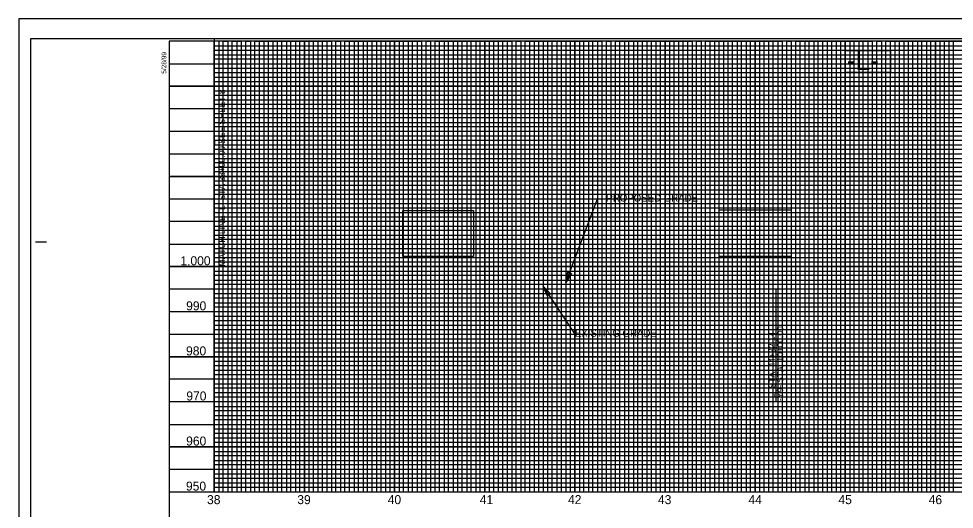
# Model space of a CAD drawing. Extents: x 1626113 to 1628102, y 900759 to 901859.
# Drawn here: x 1626113 to 1627151, y 901315 to 901859 of the extents above; entities that cross this region are included whole.
import ezdxf

# ---------------------------------------------------------------- set-up
doc = ezdxf.new("R2010")
doc.units = 0
for name, color, linetype in [('Default', 7, 'Continuous'), ('Matchline', 7, 'Continuous'), ('Matchline Text', 7, 'Continuous'), ('Prop DSN Text', 7, 'Continuous'), ('Prop PHM Black Shape', 7, 'Continuous'), ('Prop Plan Preparation Cover Label', 7, 'Continuous'), ('Scratch_Level_1', 7, 'Continuous'), ('Sheet Cutting Line CELL', 7, 'Continuous'), ('Sheet DOT Grid CELL', 7, 'Continuous'), ('Sheet Layout Profile Border Port 1', 7, 'Continuous'), ('Sheet Plot Border Inside CELL', 7, 'Continuous'), ('Sheet Plot Border Outside CELL', 7, 'Continuous'), ('Sheet Profile CELL', 7, 'Continuous'), ('Sheet Profile Grid Major CELL', 7, 'Continuous'), ('Sheet Profile Grid Middle CELL', 7, 'Continuous'), ('Typical Terminator CELL', 7, 'Continuous')]:
    doc.layers.add(name, color=color, linetype=linetype)

msp = doc.modelspace()

# ---------------------------------------------------------------- linework, layer by layer
at = {"layer": 'Matchline'}
msp.add_line((1626329.9, 901837), (1626329.9, 901334.4), dxfattribs=at)
at = {"layer": 'Prop DSN Text'}
for p, q in [((1626719.9, 901566.7), (1626754.9, 901659.4)), ((1626754.9, 901659.4), (1626764.9, 901659.4)), ((1626694.9, 901562.3), (1626729.9, 901509.4)), ((1626729.9, 901509.4), (1626734.9, 901509.4))]:
    msp.add_line(p, q, dxfattribs=at)
msp.add_lwpolyline([(1627029.9, 901824.3), (1627079.9, 901824.3), (1627079.9, 901799.4), (1627029.9, 901799.4)], close=True, dxfattribs=at)
msp.add_lwpolyline([(1626952.9, 901559.1), (1626952.9, 901434.8)], dxfattribs=at)
at = {"layer": 'Prop PHM Black Shape'}
for points in [[(1627029.9, 901824), (1627079.9, 901824), (1627079.9, 901799.2), (1627029.9, 901799.2)], [(1626539.2, 901646.5), (1626617.4, 901646.5), (1626617.4, 901595.5), (1626539.2, 901595.5)], [(1626889.9, 901647.1), (1626969.9, 901647.1), (1626969.9, 901595.6), (1626889.9, 901595.6)]]:
    msp.add_lwpolyline(points, close=True, dxfattribs=at)
at = {"layer": 'Prop Plan Preparation Cover Label'}
for p, q in [((1626329.9, 901829.2), (1627579.9, 901829.2)), ((1626329.9, 901824.2), (1626329.9, 901824.2)), ((1627579.9, 901824.2), (1626329.9, 901823.8)), ((1626329.9, 901819.2), (1627579.9, 901819.2)), ((1627579.9, 901699.2), (1626329.9, 901699.2)), ((1627579.9, 901694.2), (1626329.9, 901694.2)), ((1627579.9, 901689.2), (1626329.9, 901689.2)), ((1626329.9, 901679.2), (1627579.9, 901679.2)), ((1627579.9, 901674.2), (1626329.9, 901674.2)), ((1626329.9, 901669.2), (1627729.9, 901669.2)), ((1627729.9, 901649.2), (1626329.9, 901649.2)), ((1626329.9, 901644.2), (1627729.9, 901644.2)), ((1627729.9, 901624.2), (1626329.9, 901624.2)), ((1626329.9, 901619.2), (1627729.9, 901619.2)), ((1627729.9, 901599.2), (1626329.9, 901599.2)), ((1626329.9, 901594.2), (1627729.9, 901594.2)), ((1627729.9, 901589.2), (1626329.9, 901589.2)), ((1626329.9, 901579.2), (1627729.9, 901579.2)), ((1627729.9, 901574.2), (1626329.9, 901574.2)), ((1626329.9, 901569.2), (1627729.9, 901569.2)), ((1627729.9, 901564.2), (1626329.9, 901564.2)), ((1626329.9, 901554.2), (1627729.9, 901554.2)), ((1627729.9, 901549.2), (1626329.9, 901549.2)), ((1626329.9, 901544.2), (1627729.9, 901544.2)), ((1627729.9, 901539.2), (1626329.9, 901539.2)), ((1626329.9, 901529.2), (1627729.9, 901529.2)), ((1627729.9, 901524.2), (1626329.9, 901524.2)), ((1626329.9, 901519.2), (1627729.9, 901519.2)), ((1627729.9, 901514.2), (1626329.9, 901514.2)), ((1626329.9, 901504.2), (1627729.9, 901504.2)), ((1627729.9, 901499.2), (1626329.9, 901499.2)), ((1626329.9, 901494.2), (1627729.9, 901494.2)), ((1627729.9, 901489.2), (1626329.9, 901489.2)), ((1626329.9, 901479.2), (1627729.9, 901479.2)), ((1627729.9, 901474.2), (1626329.9, 901474.2)), ((1626329.9, 901469.2), (1627729.9, 901469.2)), ((1627729.9, 901464.2), (1626329.9, 901464.2)), ((1626329.9, 901454.2), (1627729.9, 901454.2)), ((1627729.9, 901449.2), (1626329.9, 901449.2)), ((1627729.9, 901444.2), (1626329.9, 901444.2)), ((1627729.9, 901439.2), (1626329.9, 901439.2)), ((1626329.9, 901429.2), (1627729.9, 901429.2)), ((1627729.9, 901424.2), (1626329.9, 901424.2)), ((1626329.9, 901419.2), (1627729.9, 901419.2)), ((1627729.9, 901414.2), (1626329.9, 901414.2)), ((1626329.9, 901404.2), (1627729.9, 901404.2)), ((1627729.9, 901399.2), (1626329.9, 901399.2)), ((1626329.9, 901394.2), (1627729.9, 901394.2)), ((1627729.9, 901389.2), (1626329.9, 901389.2)), ((1626329.9, 901379.2), (1627729.9, 901379.2)), ((1627729.9, 901374.2), (1626329.9, 901374.2)), ((1626329.9, 901369.2), (1627729.9, 901369.2)), ((1627729.9, 901364.2), (1626329.9, 901364.2)), ((1626329.9, 901354.2), (1627729.9, 901354.2)), ((1627729.9, 901349.2), (1626329.9, 901349.2)), ((1626329.9, 901344.2), (1627729.9, 901344.2))]:
    msp.add_line(p, q, dxfattribs=at)
for points in [[(1626334.9, 901834.2), (1626334.9, 901334.2), (1626339.9, 901334.2), (1626339.9, 901834.2), (1626344.9, 901834.2), (1626344.9, 901334.2), (1626349.9, 901334.2), (1626349.9, 901834.2), (1626359.9, 901834.2), (1626359.9, 901334.2), (1626364.9, 901334.2), (1626364.9, 901834.2), (1626369.9, 901834.2), (1626369.9, 901334.2), (1626374.9, 901334.2), (1626384.9, 901334.2), (1626389.9, 901334.2), (1626389.9, 901834.2), (1626394.9, 901834.2), (1626394.9, 901334.2), (1626399.9, 901334.2), (1626399.9, 901834.2), (1626409.9, 901834.2), (1626409.9, 901334.2), (1626414.9, 901334.2), (1626414.9, 901834.2), (1626419.9, 901834.2), (1626419.9, 901334.2), (1626424.9, 901334.2), (1626424.9, 901834.2), (1626434.9, 901834.2), (1626434.9, 901334.2), (1626439.9, 901334.2), (1626439.9, 901834.2), (1626444.9, 901834.2), (1626444.9, 901334.2), (1626449.9, 901334.2), (1626449.9, 901834.2), (1626459.9, 901834.2), (1626459.9, 901334.2), (1626464.9, 901334.2), (1626464.9, 901834.2), (1626469.9, 901834.2), (1626469.9, 901334.2), (1626474.9, 901334.2), (1626474.9, 901834.2), (1626484.9, 901834.2), (1626484.9, 901334.2), (1626489.9, 901334.2), (1626489.9, 901834.2), (1626494.9, 901834.2), (1626494.9, 901334.2), (1626499.9, 901334.2), (1626499.9, 901834.2), (1626509.9, 901834.2), (1626509.9, 901334.2), (1626514.9, 901334.2), (1626514.9, 901834.2), (1626519.9, 901834.2), (1626519.9, 901334.2), (1626524.9, 901334.2), (1626524.9, 901834.2), (1626534.9, 901834.2), (1626534.9, 901334.2), (1626539.9, 901334.2), (1626539.9, 901834.2), (1626544.9, 901834.2), (1626544.9, 901334.2)], [(1626374.9, 901334.2), (1626374.9, 901834.2), (1626384.9, 901834.2), (1626384.9, 901334.2)], [(1626544.9, 901334.2), (1626549.9, 901334.2), (1626549.9, 901834.2), (1626559.9, 901834.2), (1626559.9, 901334.2), (1626564.9, 901334.2), (1626564.9, 901834.2), (1626569.9, 901834.2), (1626569.9, 901334.2), (1626574.9, 901334.2), (1626574.9, 901834.2), (1626584.9, 901834.2), (1626584.9, 901334.2), (1626589.9, 901334.2), (1626589.9, 901834.2), (1626594.9, 901834.2), (1626594.9, 901334.2), (1626599.9, 901334.2), (1626599.9, 901834.2), (1626609.9, 901834.2), (1626609.9, 901334.2), (1626614.9, 901334.2), (1626614.9, 901834.2), (1626619.9, 901834.2), (1626619.9, 901334.2), (1626624.9, 901334.2), (1626624.9, 901834.2), (1626634.9, 901834.2), (1626634.9, 901334.2), (1626639.9, 901334.2), (1626639.9, 901834.2), (1626644.9, 901834.2), (1626644.9, 901334.2), (1626649.9, 901334.2), (1626649.9, 901834.2), (1626659.9, 901834.2), (1626659.9, 901334.2), (1626664.9, 901334.2), (1626664.9, 901834.2), (1626669.9, 901834.2), (1626669.9, 901334.2), (1626674.9, 901334.2), (1626674.9, 901834.2), (1626684.9, 901834.2), (1626684.9, 901334.2), (1626689.9, 901334.2), (1626689.9, 901834.2), (1626694.9, 901834.2), (1626694.9, 901334.2), (1626699.9, 901334.2), (1626699.9, 901834.2), (1626709.9, 901834.2), (1626709.9, 901334.2), (1626714.9, 901334.2), (1626714.9, 901834.2), (1626719.9, 901834.2), (1626719.9, 901334.2), (1626724.9, 901334.2), (1626724.9, 901834.2), (1626734.9, 901834.2), (1626734.9, 901334.2), (1626739.9, 901334.2), (1626739.9, 901834.2), (1626744.9, 901834.2), (1626744.9, 901334.2), (1626749.9, 901334.2), (1626749.9, 901834.2), (1626759.9, 901834.2), (1626759.9, 901334.2), (1626764.9, 901334.2), (1626764.9, 901834.2), (1626769.9, 901834.2), (1626769.9, 901334.2), (1626774.9, 901334.2), (1626774.9, 901834.2), (1626784.9, 901834.2), (1626784.9, 901334.2), (1626789.9, 901334.2), (1626789.9, 901834.2), (1626794.9, 901834.2), (1626794.9, 901334.2), (1626799.9, 901334.2), (1626799.9, 901834.2), (1626809.9, 901834.2), (1626809.9, 901334.2), (1626814.9, 901334.2), (1626814.9, 901834.2), (1626819.9, 901834.2), (1626819.9, 901334.2), (1626824.9, 901334.2), (1626824.9, 901834.2), (1626834.9, 901834.2), (1626834.9, 901334.2), (1626839.9, 901334.2), (1626839.9, 901834.2), (1626844.9, 901834.2), (1626844.9, 901334.2), (1626849.9, 901334.2), (1626849.9, 901834.2), (1626859.9, 901834.2)], [(1626859.9, 901834.2), (1626859.9, 901334.2), (1626864.9, 901334.2), (1626864.9, 901834.2), (1626869.9, 901834.2), (1626869.9, 901334.2), (1626874.9, 901334.2), (1626874.9, 901834.2), (1626884.9, 901834.2), (1626884.9, 901334.2), (1626889.9, 901334.2), (1626889.9, 901834.2), (1626894.9, 901834.2), (1626894.9, 901334.2), (1626899.9, 901334.2), (1626899.9, 901834.2), (1626909.9, 901834.2), (1626909.9, 901334.2), (1626914.9, 901334.2), (1626914.9, 901834.2), (1626919.9, 901834.2), (1626919.9, 901334.2), (1626924.9, 901334.2), (1626924.9, 901834.2), (1626934.9, 901834.2), (1626934.9, 901334.2), (1626939.9, 901334.2), (1626939.9, 901834.2), (1626944.9, 901834.2), (1626944.9, 901334.2), (1626949.9, 901334.2), (1626949.9, 901834.2), (1626959.9, 901834.2), (1626959.9, 901334.2), (1626964.9, 901334.2), (1626964.9, 901834.2), (1626969.9, 901834.2), (1626969.9, 901334.2), (1626974.9, 901334.2), (1626974.9, 901834.2), (1626984.9, 901834.2), (1626984.9, 901334.2), (1626984.9, 901334.2), (1626989.9, 901334.2), (1626989.9, 901834.2), (1626994.9, 901834.2), (1626994.9, 901334.2), (1626999.9, 901334.2), (1626999.9, 901834.2), (1627009.9, 901834.2), (1627009.9, 901334.2), (1627014.9, 901334.2), (1627014.9, 901834.2), (1627019.9, 901834.2), (1627019.9, 901334.2), (1627024.9, 901334.2), (1627024.9, 901834.2), (1627034.9, 901834.2), (1627034.9, 901334.2), (1627039.9, 901334.2), (1627039.9, 901834.2), (1627044.9, 901834.2), (1627044.9, 901334.2), (1627049.9, 901334.2), (1627049.9, 901834.2), (1627059.9, 901834.2), (1627059.9, 901334.2), (1627064.9, 901334.2), (1627064.9, 901834.2), (1627069.9, 901834.2), (1627069.9, 901334.2), (1627074.9, 901334.2), (1627074.9, 901834.2), (1627084.9, 901834.2), (1627084.9, 901334.2), (1627089.9, 901334.2), (1627089.9, 901834.2), (1627094.9, 901834.2), (1627094.9, 901334.2), (1627099.9, 901334.2), (1627099.9, 901834.2), (1627109.9, 901834.2), (1627109.9, 901334.2), (1627114.9, 901334.2), (1627114.9, 901834.2), (1627119.9, 901834.2), (1627119.9, 901334.2), (1627124.9, 901334.2), (1627124.9, 901834.2), (1627134.9, 901834.2), (1627134.9, 901334.2), (1627139.6, 901334.7), (1627139.9, 901334.2), (1627139.9, 901834.2), (1627144.9, 901834.2), (1627144.9, 901334.2), (1627149.9, 901334.2), (1627149.9, 901834.2), (1627159.9, 901834.2)], [(1627579.9, 901814.2), (1626329.9, 901814.2), (1626329.9, 901804.2), (1627579.9, 901804.2)], [(1627579.9, 901799.2), (1626329.9, 901799.2), (1626329.9, 901794.2), (1627579.9, 901794.2)], [(1627579.9, 901789.2), (1626329.9, 901789.2), (1626329.9, 901779.2), (1627579.9, 901779.2)], [(1627579.9, 901774.2), (1626329.9, 901774.2), (1626329.9, 901769.2), (1627579.9, 901769.2)], [(1627579.9, 901764.2), (1626329.9, 901764.2), (1626329.9, 901754.2), (1627579.9, 901754.2)], [(1627579.9, 901749.2), (1626329.9, 901749.2), (1626329.9, 901744.2), (1627579.9, 901744.2)], [(1627579.9, 901739.2), (1626329.9, 901739.2), (1626329.9, 901729.2), (1627579.9, 901729.2)], [(1627579.9, 901724.1), (1626330, 901724.1), (1626330, 901719.2), (1627579.9, 901719.2)], [(1627579.9, 901714.2), (1626329.9, 901714.2), (1626329.9, 901704.2), (1627579.9, 901704.2)], [(1627729.9, 901664.2), (1626329.9, 901664.2), (1626329.9, 901654.2), (1627729.9, 901654.2)], [(1627729.9, 901639.2), (1626329.9, 901639.2), (1626329.9, 901629.2), (1627729.9, 901629.2)], [(1627729.9, 901614.2), (1626329.9, 901614.2), (1626329.9, 901604.2), (1627729.9, 901604.2)], [(1627729.9, 901339.2), (1626329.9, 901339.2)]]:
    msp.add_lwpolyline(points, dxfattribs=at)
at = {"layer": 'Scratch_Level_1'}
msp.add_lwpolyline([(1626329.9, 901334.4), (1627529.9, 901334.4), (1627529.9, 901834.4), (1626329.9, 901834.4)], close=True, dxfattribs=at)
at = {"layer": 'Sheet Cutting Line CELL'}
for p, q in [((1627796.9, 901859.2), (1626112.9, 901859.2)), ((1626112.9, 901859.2), (1626112.9, 900759.2))]:
    msp.add_line(p, q, dxfattribs=at)
at = {"layer": 'Sheet DOT Grid CELL'}
for p, q in [((1626329.9, 901334.2), (1626329.9, 901834.2)), ((1626379.9, 901334.2), (1626379.9, 901834.2)), ((1626429.9, 901334.2), (1626429.9, 901834.2)), ((1626479.9, 901334.2), (1626479.9, 901834.2)), ((1626529.9, 901334.2), (1626529.9, 901834.2)), ((1626579.9, 901334.2), (1626579.9, 901834.2)), ((1626629.9, 901334.2), (1626629.9, 901834.2)), ((1626679.9, 901334.2), (1626679.9, 901834.2)), ((1626729.9, 901334.2), (1626729.9, 901834.2)), ((1626779.9, 901334.2), (1626779.9, 901834.2)), ((1626829.9, 901334.2), (1626829.9, 901834.2)), ((1626879.9, 901334.2), (1626879.9, 901834.2)), ((1626929.9, 901334.2), (1626929.9, 901834.2)), ((1626979.9, 901334.2), (1626979.9, 901834.2)), ((1627029.9, 901334.2), (1627029.9, 901834.2)), ((1627079.9, 901334.2), (1627079.9, 901834.2)), ((1627129.9, 901334.2), (1627129.9, 901834.2)), ((1627579.9, 901784.2), (1626279.9, 901784.2)), ((1627579.9, 901734.2), (1626279.9, 901734.2)), ((1627579.9, 901684.2), (1626279.9, 901684.2)), ((1627779.9, 901634.2), (1626279.9, 901634.2)), ((1627779.9, 901584.2), (1626279.9, 901584.2)), ((1627779.9, 901534.2), (1626279.9, 901534.2)), ((1627779.9, 901484.2), (1626279.9, 901484.2)), ((1627779.9, 901434.2), (1626279.9, 901434.2)), ((1627779.9, 901384.2), (1626279.9, 901384.2))]:
    msp.add_line(p, q, dxfattribs=at)
at = {"layer": 'Sheet Layout Profile Border Port 1'}
msp.add_lwpolyline([(1626329.9, 901673.1), (1626329.9, 901334.2), (1627729.9, 901334.2), (1627729.9, 901673.1)], dxfattribs=at)
at = {"layer": 'Sheet Plot Border Inside CELL'}
msp.add_lwpolyline([(1626125.9, 900781.6), (1627792.4, 900781.6), (1627792.4, 901836.7), (1626125.9, 901836.7)], close=True, dxfattribs=at)
at = {"layer": 'Sheet Plot Border Outside CELL'}
msp.add_lwpolyline([(1626112.9, 900759.2), (1627796.9, 900759.2), (1627796.9, 901859.2), (1626112.9, 901859.2)], close=True, dxfattribs=at)
at = {"layer": 'Sheet Profile CELL'}
for p, q in [((1626131.4, 901611.7), (1626143.9, 901611.7)), ((1626279.9, 901334.2), (1627779.9, 901334.2))]:
    msp.add_line(p, q, dxfattribs=at)
msp.add_lwpolyline([(1627779.9, 901834.2), (1626279.9, 901834.2), (1626279.9, 900784.2), (1627779.9, 900784.2)], close=True, dxfattribs=at)
at = {"layer": 'Sheet Profile Grid Major CELL'}
for points in [[(1626329.9, 901834.2), (1626329.9, 901334.2), (1626379.9, 901334.2), (1626379.9, 901834.2), (1626429.9, 901834.2), (1626429.9, 901334.2), (1626479.9, 901334.2), (1626479.9, 901834.2), (1626529.9, 901834.2), (1626529.9, 901334.2), (1626579.9, 901334.2), (1626579.9, 901834.2), (1626629.9, 901834.2), (1626629.9, 901334.2), (1626679.9, 901334.2), (1626679.9, 901834.2), (1626729.9, 901834.2), (1626729.9, 901334.2), (1626779.9, 901334.2), (1626779.9, 901834.2), (1626829.9, 901834.2), (1626829.9, 901334.2), (1626879.9, 901334.2), (1626879.9, 901834.2), (1626929.9, 901834.2), (1626929.9, 901334.2), (1626979.9, 901334.2), (1626979.9, 901834.2), (1627029.9, 901834.2), (1627029.9, 901334.2), (1627079.9, 901334.2), (1627079.9, 901834.2), (1627129.9, 901834.2), (1627129.9, 901334.2), (1627179.9, 901334.2)], [(1626279.9, 901784.2), (1627579.9, 901784.2)], [(1627579.9, 901734.2), (1626279.9, 901734.2), (1626279.9, 901684.2), (1627579.9, 901684.2)], [(1627779.9, 901634.2), (1626279.9, 901634.2), (1626279.9, 901584.2), (1627779.9, 901584.2)], [(1627779.9, 901534.2), (1626279.9, 901534.2), (1626279.9, 901484.2), (1627779.9, 901484.2)], [(1627779.9, 901434.2), (1626279.9, 901434.2), (1626279.9, 901434.2), (1626279.9, 901384.2), (1627779.9, 901384.2)]]:
    msp.add_lwpolyline(points, dxfattribs=at)
at = {"layer": 'Sheet Profile Grid Middle CELL'}
msp.add_line((1626279.9, 901809.2), (1627579.9, 901809.2), dxfattribs=at)
for points in [[(1626354.9, 901834.2), (1626354.9, 901334.2), (1626404.9, 901334.2), (1626404.9, 901834.2), (1626454.9, 901834.2), (1626454.9, 901334.2), (1626504.9, 901334.2), (1626504.9, 901834.2), (1626554.9, 901834.2), (1626554.9, 901334.2), (1626604.9, 901334.2), (1626604.9, 901834.2), (1626654.9, 901834.2), (1626654.9, 901334.2), (1626704.9, 901334.2), (1626704.9, 901834.2), (1626754.9, 901834.2), (1626754.9, 901334.2), (1626804.9, 901334.2), (1626804.9, 901834.2), (1626854.9, 901834.2), (1626854.9, 901334.2), (1626904.9, 901334.2), (1626904.9, 901334.2), (1626904.9, 901834.2), (1626954.9, 901834.2), (1626954.9, 901334.2), (1627004.9, 901334.2), (1627004.9, 901834.2), (1627054.9, 901834.2), (1627054.9, 901334.2), (1627104.9, 901334.2), (1627104.9, 901834.2), (1627154.9, 901834.2)], [(1627579.9, 901759.2), (1626279.9, 901759.2), (1626279.9, 901709.2), (1627579.9, 901709.2)], [(1627779.9, 901659.2), (1626279.9, 901659.2), (1626279.9, 901609.2), (1627604.9, 901609.2)], [(1627779.9, 901559.2), (1626279.9, 901559.2), (1626279.9, 901509.2), (1627779.9, 901509.2)], [(1627779.9, 901459.2), (1626279.9, 901459.2), (1626279.9, 901409.2), (1627779.9, 901409.2)], [(1627779.9, 901359.2), (1626279.9, 901359.2)]]:
    msp.add_lwpolyline(points, dxfattribs=at)
at = {"layer": 'Typical Terminator CELL'}
for points in [[(1626726, 901576.9), (1626719.9, 901566.7), (1626722.2, 901578.5), (1626723.6, 901576.3)], [(1626726, 901576.9), (1626719.9, 901566.7), (1626722.2, 901578.5), (1626723.6, 901576.3)], [(1626726, 901576.9), (1626719.9, 901566.7), (1626722.2, 901578.5), (1626723.6, 901576.3)], [(1626721.2, 901568.7), (1626719.9, 901566.7), (1626720.4, 901569), (1626720.7, 901568.6)], [(1626695.9, 901560.2), (1626694.9, 901562.3), (1626696.6, 901560.6), (1626696.1, 901560.6)], [(1626695.9, 901560.2), (1626694.9, 901562.3), (1626696.6, 901560.6), (1626696.1, 901560.6)], [(1626699.7, 901551.5), (1626694.9, 901562.3), (1626703.2, 901553.7), (1626700.6, 901553.8)], [(1626699.7, 901551.5), (1626694.9, 901562.3), (1626703.2, 901553.7), (1626700.6, 901553.8)]]:
    msp.add_lwpolyline(points, close=True, dxfattribs=at)

# ---------------------------------------------------------------- texts
at = {"layer": 'Default'}
for s, p in [('1,000', (1626292.3, 901585.7)), ('990', (1626298.7, 901535.7)), ('980', (1626298.6, 901485.7)), ('970', (1626298.9, 901435.7)), ('960', (1626298.7, 901385.7)), ('950', (1626298.5, 901335.7)), ('38', (1626321.9, 901320.7)), ('39', (1626422, 901320.7)), ('40', (1626522.3, 901320.7)), ('41', (1626624.4, 901320.7)), ('42', (1626722.3, 901320.7)), ('43', (1626822.1, 901320.7)), ('44', (1626922.5, 901320.7)), ('45', (1627022.3, 901320.7)), ('46', (1627122.4, 901320.7))]:
    msp.add_text(s, height=10, dxfattribs=at).set_placement(p)
at = {"layer": 'Matchline Text'}
msp.add_text('MATCH LINE -L- STA 38+00.00 SEE SHEET 8', height=7, rotation=90, dxfattribs=at).set_placement((1626341.9, 901584.4))
at = {"layer": 'Prop DSN Text'}
for s, height, p in [('-L-', 21.88, (1627031.5, 901802.2)), ('PROPOSED GRADE', 8, (1626764.9, 901656.4)), ('EXISTING GRADE', 8, (1626729.9, 901506.4))]:
    msp.add_text(s, height=height, dxfattribs=at).set_placement(p)
for s, p in [('-Y9- STA. 10+00.00', (1626961, 901435.1)), ('-L- STA. 44+32.14', (1626952.1, 901435.1))]:
    msp.add_text(s, height=7, rotation=90, dxfattribs=at).set_placement(p)
at = {"layer": 'Sheet Profile CELL'}
msp.add_text('5/28/99', height=5.25, rotation=90, dxfattribs=at).set_placement((1626276.7, 901798.1))

doc.saveas('drawing.dxf')
